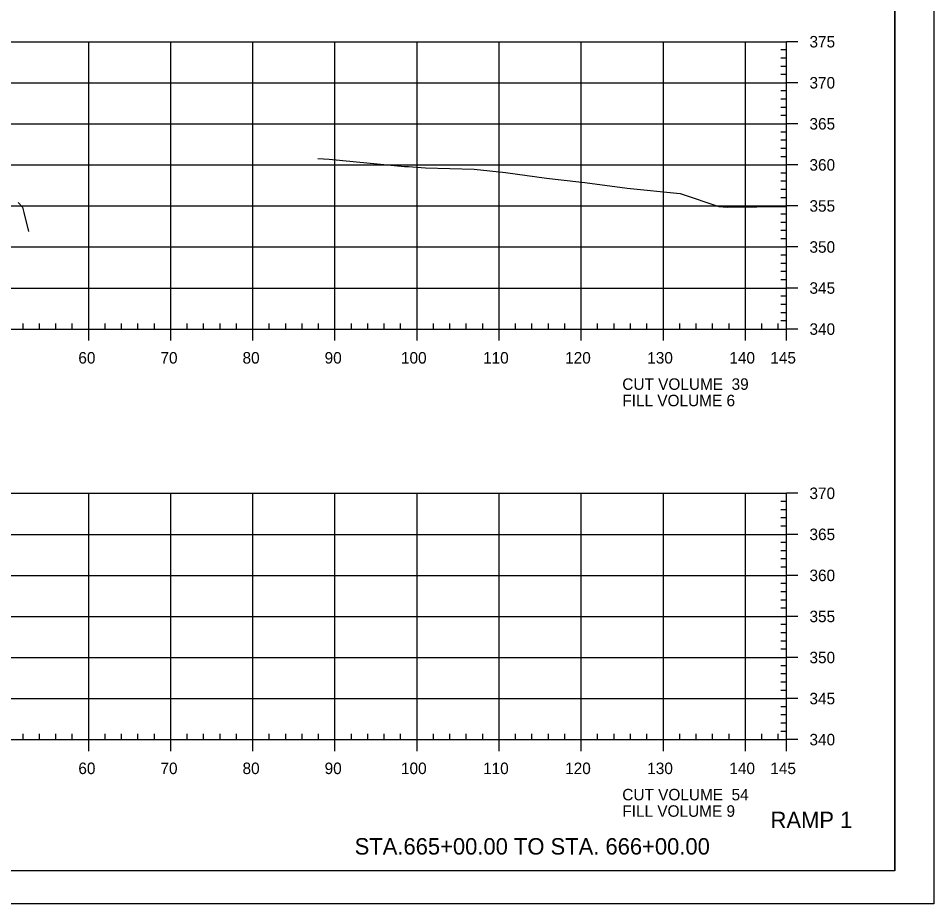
# Model space of a CAD drawing. Extents: x 1359801 to 1362404, y 372415 to 374228.
# Drawn here: x 1360022.8 to 1360134.3, y 373374.6 to 373482.5 of the extents above; entities that cross this region are included whole.
import ezdxf

# ---------------------------------------------------------------- set-up
doc = ezdxf.new("R2010")
doc.units = 0
for name, color, linetype in [('S_DRG_PT_SYM', 7, 'Continuous'), ('S_MAILBOX', 7, 'Continuous'), ('S_PRIMARY_CTL', 7, 'Continuous'), ('S_SHOULDER', 7, 'Continuous'), ('S_SIGN', 7, 'Continuous'), ('S_UTL_PT_SYM', 7, 'Continuous'), ('S_WATER_UTILITIES', 7, 'Continuous')]:
    doc.layers.add(name, color=color, linetype=linetype)

msp = doc.modelspace()

# ---------------------------------------------------------------- linework, layer by layer
at = {"layer": 'S_DRG_PT_SYM'}
for points in [[(1360059.28, 373465.38), (1360060.64, 373465.28), (1360069.83, 373464.42), (1360070.31, 373464.39), (1360070.8, 373464.36), (1360072.36, 373464.26), (1360078.29, 373464.09), (1360082.14, 373463.68), (1360087.1, 373462.99), (1360091.05, 373462.54), (1360091.8, 373462.47), (1360096.93, 373461.77), (1360103.38, 373461.1), (1360103.52, 373461.06), (1360108.1, 373459.54), (1360109.12, 373459.44), (1360116.35, 373459.52)], [(1360022.76, 373460), (1360023.28, 373459.45), (1360023.43, 373458.82), (1360024, 373456.5)]]:
    msp.add_lwpolyline(points, dxfattribs=at)
at = {"layer": 'S_MAILBOX'}
for p, q in [((1359826.35, 373479.6), (1360116.35, 373479.6)), ((1359826.35, 373479.6), (1360116.35, 373479.6)), ((1360031.35, 373444.6), (1360031.35, 373479.6)), ((1360031.35, 373444.6), (1360031.35, 373479.6)), ((1360041.35, 373444.6), (1360041.35, 373479.6)), ((1360041.35, 373444.6), (1360041.35, 373479.6)), ((1360051.35, 373444.6), (1360051.35, 373479.6)), ((1360051.35, 373444.6), (1360051.35, 373479.6)), ((1360061.35, 373444.6), (1360061.35, 373479.6)), ((1360061.35, 373444.6), (1360061.35, 373479.6)), ((1360071.35, 373444.6), (1360071.35, 373479.6)), ((1360071.35, 373444.6), (1360071.35, 373479.6)), ((1360081.35, 373444.6), (1360081.35, 373479.6)), ((1360081.35, 373444.6), (1360081.35, 373479.6)), ((1360091.35, 373444.6), (1360091.35, 373479.6)), ((1360091.35, 373444.6), (1360091.35, 373479.6)), ((1360101.35, 373444.6), (1360101.35, 373479.6)), ((1360101.35, 373444.6), (1360101.35, 373479.6)), ((1360111.35, 373444.6), (1360111.35, 373479.6)), ((1360111.35, 373444.6), (1360111.35, 373479.6)), ((1360116.35, 373444.6), (1360116.35, 373479.6)), ((1360116.35, 373444.6), (1360116.35, 373479.6)), ((1359826.35, 373474.6), (1360116.35, 373474.6)), ((1359826.35, 373474.6), (1360116.35, 373474.6)), ((1359826.35, 373469.6), (1360116.35, 373469.6)), ((1359826.35, 373469.6), (1360116.35, 373469.6)), ((1359826.35, 373464.6), (1360116.35, 373464.6)), ((1359826.35, 373464.6), (1360116.35, 373464.6)), ((1359826.35, 373459.6), (1360116.35, 373459.6)), ((1359826.35, 373459.6), (1360116.35, 373459.6)), ((1359826.35, 373454.6), (1360116.35, 373454.6)), ((1359826.35, 373454.6), (1360116.35, 373454.6)), ((1359826.35, 373449.6), (1360116.35, 373449.6)), ((1359826.35, 373449.6), (1360116.35, 373449.6)), ((1359826.35, 373444.6), (1360116.35, 373444.6)), ((1359826.35, 373444.6), (1360116.35, 373444.6)), ((1359826.35, 373424.6), (1360116.35, 373424.6)), ((1360031.35, 373394.6), (1360031.35, 373424.6)), ((1360041.35, 373394.6), (1360041.35, 373424.6)), ((1360051.35, 373394.6), (1360051.35, 373424.6)), ((1360061.35, 373394.6), (1360061.35, 373424.6)), ((1360071.35, 373394.6), (1360071.35, 373424.6)), ((1360081.35, 373394.6), (1360081.35, 373424.6)), ((1360091.35, 373394.6), (1360091.35, 373424.6)), ((1360101.35, 373394.6), (1360101.35, 373424.6)), ((1360111.35, 373394.6), (1360111.35, 373424.6)), ((1360116.35, 373394.6), (1360116.35, 373424.6)), ((1359826.35, 373419.6), (1360116.35, 373419.6)), ((1359826.35, 373414.6), (1360116.35, 373414.6)), ((1359826.35, 373409.6), (1360116.35, 373409.6)), ((1359826.35, 373404.6), (1360116.35, 373404.6)), ((1359826.35, 373399.6), (1360116.35, 373399.6)), ((1359826.35, 373394.6), (1360116.35, 373394.6))]:
    msp.add_line(p, q, dxfattribs=at)
at = {"layer": 'S_SHOULDER'}
msp.add_line((1359800.95, 373374.62), (1360134.28, 373374.62), dxfattribs=at)
for points in [[(1359800.94, 373587.95), (1360134.28, 373587.95), (1360134.28, 373374.61), (1359800.94, 373374.61)], [(1360047.27, 373584.06), (1360047.27, 373574.18), (1360083, 373574.18), (1360083, 373571.26), (1360106.2, 373571.26), (1360106.2, 373546.93), (1360129.53, 373546.93), (1360129.53, 373378.6), (1359813.35, 373378.6), (1359813.35, 373584.06)]]:
    msp.add_lwpolyline(points, close=True, dxfattribs=at)
at = {"layer": 'S_UTL_PT_SYM'}
for q in [(1360129.53, 373584.06), (1359813.35, 373378.6)]:
    msp.add_line((1360129.53, 373378.6), q, dxfattribs=at)
at = {"layer": 'S_WATER_UTILITIES'}
for p, q in [((1360116.35, 373444.6), (1360116.35, 373479.6)), ((1360117.75, 373479.6), (1360116.35, 373479.6)), ((1360116.35, 373478.6), (1360115.65, 373478.6)), ((1360116.35, 373477.6), (1360115.65, 373477.6)), ((1360116.35, 373476.6), (1360115.65, 373476.6)), ((1360116.35, 373475.6), (1360115.65, 373475.6)), ((1360117.75, 373474.6), (1360116.35, 373474.6)), ((1360116.35, 373473.6), (1360115.65, 373473.6)), ((1360116.35, 373472.6), (1360115.65, 373472.6)), ((1360116.35, 373471.6), (1360115.65, 373471.6)), ((1360116.35, 373470.6), (1360115.65, 373470.6)), ((1360117.75, 373469.6), (1360116.35, 373469.6)), ((1360116.35, 373468.6), (1360115.65, 373468.6)), ((1360116.35, 373467.6), (1360115.65, 373467.6)), ((1360116.35, 373466.6), (1360115.65, 373466.6)), ((1360116.35, 373465.6), (1360115.65, 373465.6)), ((1360117.75, 373464.6), (1360116.35, 373464.6)), ((1360116.35, 373463.6), (1360115.65, 373463.6)), ((1360116.35, 373462.6), (1360115.65, 373462.6)), ((1360116.35, 373461.6), (1360115.65, 373461.6)), ((1360116.35, 373460.6), (1360115.65, 373460.6)), ((1360117.75, 373459.6), (1360116.35, 373459.6)), ((1360116.35, 373458.6), (1360115.65, 373458.6)), ((1360116.35, 373457.6), (1360115.65, 373457.6)), ((1360116.35, 373456.6), (1360115.65, 373456.6)), ((1360116.35, 373455.6), (1360115.65, 373455.6)), ((1360117.75, 373454.6), (1360116.35, 373454.6)), ((1360116.35, 373453.6), (1360115.65, 373453.6)), ((1360116.35, 373452.6), (1360115.65, 373452.6)), ((1360116.35, 373451.6), (1360115.65, 373451.6)), ((1360116.35, 373450.6), (1360115.65, 373450.6)), ((1360117.75, 373449.6), (1360116.35, 373449.6)), ((1360116.35, 373448.6), (1360115.65, 373448.6)), ((1360116.35, 373447.6), (1360115.65, 373447.6)), ((1360116.35, 373446.6), (1360115.65, 373446.6)), ((1360116.35, 373445.6), (1360115.65, 373445.6)), ((1359826.35, 373444.6), (1360116.35, 373444.6)), ((1360023.35, 373444.6), (1360023.35, 373445.3)), ((1360025.35, 373444.6), (1360025.35, 373445.3)), ((1360027.35, 373444.6), (1360027.35, 373445.3)), ((1360029.35, 373444.6), (1360029.35, 373445.3)), ((1360031.35, 373443.2), (1360031.35, 373444.6)), ((1360033.35, 373444.6), (1360033.35, 373445.3)), ((1360035.35, 373444.6), (1360035.35, 373445.3)), ((1360037.35, 373444.6), (1360037.35, 373445.3)), ((1360039.35, 373444.6), (1360039.35, 373445.3)), ((1360041.35, 373443.2), (1360041.35, 373444.6)), ((1360043.35, 373444.6), (1360043.35, 373445.3)), ((1360045.35, 373444.6), (1360045.35, 373445.3)), ((1360047.35, 373444.6), (1360047.35, 373445.3)), ((1360049.35, 373444.6), (1360049.35, 373445.3)), ((1360051.35, 373443.2), (1360051.35, 373444.6)), ((1360053.35, 373444.6), (1360053.35, 373445.3)), ((1360055.35, 373444.6), (1360055.35, 373445.3)), ((1360057.35, 373444.6), (1360057.35, 373445.3)), ((1360059.35, 373444.6), (1360059.35, 373445.3)), ((1360061.35, 373443.2), (1360061.35, 373444.6)), ((1360063.35, 373444.6), (1360063.35, 373445.3)), ((1360065.35, 373444.6), (1360065.35, 373445.3)), ((1360067.35, 373444.6), (1360067.35, 373445.3)), ((1360069.35, 373444.6), (1360069.35, 373445.3)), ((1360071.35, 373443.2), (1360071.35, 373444.6)), ((1360073.35, 373444.6), (1360073.35, 373445.3)), ((1360075.35, 373444.6), (1360075.35, 373445.3)), ((1360077.35, 373444.6), (1360077.35, 373445.3)), ((1360079.35, 373444.6), (1360079.35, 373445.3)), ((1360081.35, 373443.2), (1360081.35, 373444.6)), ((1360083.35, 373444.6), (1360083.35, 373445.3)), ((1360085.35, 373444.6), (1360085.35, 373445.3)), ((1360087.35, 373444.6), (1360087.35, 373445.3)), ((1360089.35, 373444.6), (1360089.35, 373445.3)), ((1360091.35, 373443.2), (1360091.35, 373444.6)), ((1360093.35, 373444.6), (1360093.35, 373445.3)), ((1360095.35, 373444.6), (1360095.35, 373445.3)), ((1360097.35, 373444.6), (1360097.35, 373445.3)), ((1360099.35, 373444.6), (1360099.35, 373445.3)), ((1360101.35, 373443.2), (1360101.35, 373444.6)), ((1360103.35, 373444.6), (1360103.35, 373445.3)), ((1360105.35, 373444.6), (1360105.35, 373445.3)), ((1360107.35, 373444.6), (1360107.35, 373445.3)), ((1360109.35, 373444.6), (1360109.35, 373445.3)), ((1360111.35, 373443.2), (1360111.35, 373444.6)), ((1360113.35, 373444.6), (1360113.35, 373445.3)), ((1360115.35, 373444.6), (1360115.35, 373445.3)), ((1360116.35, 373443.2), (1360116.35, 373444.6)), ((1360117.75, 373444.6), (1360116.35, 373444.6)), ((1360116.35, 373394.6), (1360116.35, 373424.6)), ((1360117.75, 373424.6), (1360116.35, 373424.6)), ((1360116.35, 373423.6), (1360115.65, 373423.6)), ((1360116.35, 373422.6), (1360115.65, 373422.6)), ((1360116.35, 373421.6), (1360115.65, 373421.6)), ((1360116.35, 373420.6), (1360115.65, 373420.6)), ((1360117.75, 373419.6), (1360116.35, 373419.6)), ((1360116.35, 373418.6), (1360115.65, 373418.6)), ((1360116.35, 373417.6), (1360115.65, 373417.6)), ((1360116.35, 373416.6), (1360115.65, 373416.6)), ((1360116.35, 373415.6), (1360115.65, 373415.6)), ((1360117.75, 373414.6), (1360116.35, 373414.6)), ((1360116.35, 373413.6), (1360115.65, 373413.6)), ((1360116.35, 373412.6), (1360115.65, 373412.6)), ((1360116.35, 373411.6), (1360115.65, 373411.6)), ((1360116.35, 373410.6), (1360115.65, 373410.6)), ((1360117.75, 373409.6), (1360116.35, 373409.6)), ((1360116.35, 373408.6), (1360115.65, 373408.6)), ((1360116.35, 373407.6), (1360115.65, 373407.6)), ((1360116.35, 373406.6), (1360115.65, 373406.6)), ((1360116.35, 373405.6), (1360115.65, 373405.6)), ((1360117.75, 373404.6), (1360116.35, 373404.6)), ((1360116.35, 373403.6), (1360115.65, 373403.6)), ((1360116.35, 373402.6), (1360115.65, 373402.6)), ((1360116.35, 373401.6), (1360115.65, 373401.6)), ((1360116.35, 373400.6), (1360115.65, 373400.6)), ((1360117.75, 373399.6), (1360116.35, 373399.6)), ((1360116.35, 373398.6), (1360115.65, 373398.6)), ((1360116.35, 373397.6), (1360115.65, 373397.6)), ((1360116.35, 373396.6), (1360115.65, 373396.6)), ((1360116.35, 373395.6), (1360115.65, 373395.6)), ((1359826.35, 373394.6), (1360116.35, 373394.6)), ((1360023.35, 373394.6), (1360023.35, 373395.3)), ((1360025.35, 373394.6), (1360025.35, 373395.3)), ((1360027.35, 373394.6), (1360027.35, 373395.3)), ((1360029.35, 373394.6), (1360029.35, 373395.3)), ((1360031.35, 373393.2), (1360031.35, 373394.6)), ((1360033.35, 373394.6), (1360033.35, 373395.3)), ((1360035.35, 373394.6), (1360035.35, 373395.3)), ((1360037.35, 373394.6), (1360037.35, 373395.3)), ((1360039.35, 373394.6), (1360039.35, 373395.3)), ((1360041.35, 373393.2), (1360041.35, 373394.6)), ((1360043.35, 373394.6), (1360043.35, 373395.3)), ((1360045.35, 373394.6), (1360045.35, 373395.3)), ((1360047.35, 373394.6), (1360047.35, 373395.3)), ((1360049.35, 373394.6), (1360049.35, 373395.3)), ((1360051.35, 373393.2), (1360051.35, 373394.6)), ((1360053.35, 373394.6), (1360053.35, 373395.3)), ((1360055.35, 373394.6), (1360055.35, 373395.3)), ((1360057.35, 373394.6), (1360057.35, 373395.3)), ((1360059.35, 373394.6), (1360059.35, 373395.3)), ((1360061.35, 373393.2), (1360061.35, 373394.6)), ((1360063.35, 373394.6), (1360063.35, 373395.3)), ((1360065.35, 373394.6), (1360065.35, 373395.3)), ((1360067.35, 373394.6), (1360067.35, 373395.3)), ((1360069.35, 373394.6), (1360069.35, 373395.3)), ((1360071.35, 373393.2), (1360071.35, 373394.6)), ((1360073.35, 373394.6), (1360073.35, 373395.3)), ((1360075.35, 373394.6), (1360075.35, 373395.3)), ((1360077.35, 373394.6), (1360077.35, 373395.3)), ((1360079.35, 373394.6), (1360079.35, 373395.3)), ((1360081.35, 373393.2), (1360081.35, 373394.6)), ((1360083.35, 373394.6), (1360083.35, 373395.3)), ((1360085.35, 373394.6), (1360085.35, 373395.3)), ((1360087.35, 373394.6), (1360087.35, 373395.3)), ((1360089.35, 373394.6), (1360089.35, 373395.3)), ((1360091.35, 373393.2), (1360091.35, 373394.6)), ((1360093.35, 373394.6), (1360093.35, 373395.3)), ((1360095.35, 373394.6), (1360095.35, 373395.3)), ((1360097.35, 373394.6), (1360097.35, 373395.3)), ((1360099.35, 373394.6), (1360099.35, 373395.3)), ((1360101.35, 373393.2), (1360101.35, 373394.6)), ((1360103.35, 373394.6), (1360103.35, 373395.3)), ((1360105.35, 373394.6), (1360105.35, 373395.3)), ((1360107.35, 373394.6), (1360107.35, 373395.3)), ((1360109.35, 373394.6), (1360109.35, 373395.3)), ((1360111.35, 373393.2), (1360111.35, 373394.6)), ((1360113.35, 373394.6), (1360113.35, 373395.3)), ((1360115.35, 373394.6), (1360115.35, 373395.3)), ((1360116.35, 373393.2), (1360116.35, 373394.6)), ((1360117.75, 373394.6), (1360116.35, 373394.6))]:
    msp.add_line(p, q, dxfattribs=at)

# ---------------------------------------------------------------- texts
at = {"layer": 'S_PRIMARY_CTL'}
for s, p in [('375', (1360119.15, 373478.9)), ('370', (1360119.15, 373473.9)), ('365', (1360119.15, 373468.9)), ('360', (1360119.15, 373463.9)), ('355', (1360119.15, 373458.9)), ('350', (1360119.15, 373453.9)), ('345', (1360119.15, 373448.9)), ('340', (1360119.15, 373443.9)), ('60', (1360030.09, 373440.4)), ('70', (1360040.09, 373440.4)), ('80', (1360050.09, 373440.4)), ('90', (1360060.09, 373440.4)), ('100', (1360069.39, 373440.4)), ('110', (1360079.39, 373440.4)), ('120', (1360089.39, 373440.4)), ('130', (1360099.39, 373440.4)), ('140', (1360109.39, 373440.4)), ('145', (1360114.38, 373440.4)), ('CUT VOLUME  39', (1360096.35, 373437.2)), ('FILL VOLUME 6', (1360096.35, 373435.2)), ('370', (1360119.15, 373423.9)), ('365', (1360119.15, 373418.9)), ('360', (1360119.15, 373413.9)), ('355', (1360119.15, 373408.9)), ('350', (1360119.15, 373403.9)), ('345', (1360119.15, 373398.9)), ('340', (1360119.15, 373393.9)), ('60', (1360030.09, 373390.4)), ('70', (1360040.09, 373390.4)), ('80', (1360050.09, 373390.4)), ('90', (1360060.09, 373390.4)), ('100', (1360069.39, 373390.4)), ('110', (1360079.39, 373390.4)), ('120', (1360089.39, 373390.4)), ('130', (1360099.39, 373390.4)), ('140', (1360109.39, 373390.4)), ('145', (1360114.38, 373390.4)), ('CUT VOLUME  54', (1360096.35, 373387.2)), ('FILL VOLUME 9', (1360096.35, 373385.2))]:
    msp.add_text(s, height=1.4, dxfattribs=at).set_placement(p)
at = {"layer": 'S_SIGN'}
for s, p in [('RAMP 1', (1360114.41, 373383.82)), ('STA.665+00.00 TO STA. 666+00.00', (1360063.75, 373380.6))]:
    msp.add_text(s, height=2, dxfattribs=at).set_placement(p)

doc.saveas('drawing.dxf')
